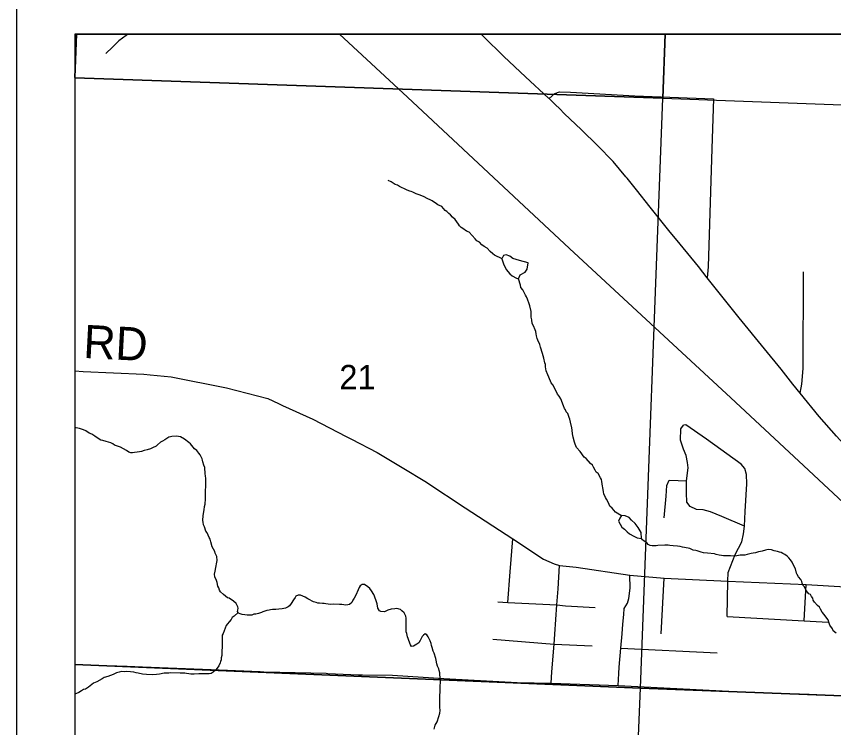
# Model space of a CAD drawing. Extents: x 0 to 34, y 0 to 22.
# Drawn here: x 2 to 3.4, y 19.712 to 20.931 of the extents above; entities that cross this region are included whole.
import ezdxf

# ---------------------------------------------------------------- set-up
doc = ezdxf.new("R2010")
doc.units = 0
for name, color, linetype in [('Default', 7, 'Continuous'), ('GM_X_City_Street', 7, 'Continuous'), ('GM_X_County_Road', 7, 'Continuous'), ('GM_X_County_Road_Text', 7, 'Continuous'), ('GM_X_Minor_River', 7, 'Continuous'), ('GM_X_Rail_Line', 7, 'Continuous'), ('GM_X_Section', 7, 'Continuous'), ('GM_X_Section_Text', 7, 'Continuous'), ('GM_X_US_Route', 7, 'Continuous'), ('SH_Data', 7, 'Continuous')]:
    doc.layers.add(name, color=color, linetype=linetype)

msp = doc.modelspace()

# ---------------------------------------------------------------- linework, layer by layer
at = {"layer": 'Default'}
for points in [[(2.1028, 20.9), (2.1, 20.9), (2.1, 20.8261)], [(2.1, 20.8261), (2.1, 20.8252), (3.1076, 20.7906), (3.1115, 20.9), (2.1028, 20.9)], [(4.1106, 20.9), (3.1115, 20.9), (3.1076, 20.7906), (4.105, 20.7535)], [(2.1, 20.8252), (2.1, 19.8201), (3.0692, 19.7796), (3.1076, 20.7906)], [(2.1, 19.8201), (2.1, 18.8072), (3.0273, 18.7832), (3.0692, 19.7796)]]:
    msp.add_lwpolyline(points, close=True, dxfattribs=at)
msp.add_lwpolyline([(6.0871, 20.9), (2.1, 20.9), (2.1, 17.8044), (2.8305, 17.7727), (2.976, 17.7664), (3.1037, 17.7609), (3.4544, 17.7458), (3.7662, 17.7368), (3.9904, 17.7296), (4.1165, 17.7286), (4.1238, 17.7269), (4.1354, 17.7264), (4.1969, 17.7246), (4.2769, 17.7222), (4.4203, 17.718), (4.506, 17.7155), (4.6237, 17.7121), (4.6735, 17.7102), (4.763, 17.7084), (4.9045, 17.7039), (4.98, 17.7015), (5.0396, 17.6997)], dxfattribs=at)
at = {"layer": 'GM_X_City_Street'}
for p, q in [((3.1047, 19.8726), (3.1096, 19.9678)), ((3.2177, 19.9023), (3.2187, 19.9627)), ((3.3493, 19.895), (3.3527, 19.9573)), ((3.0356, 19.8482), (3.2002, 19.8402))]:
    msp.add_line(p, q, dxfattribs=at)
for points in [[(2.9126, 20.7897), (2.9223, 20.7987), (2.9306, 20.8011), (2.9494, 20.8007), (3.0593, 20.7945), (3.194, 20.7893), (3.1915, 20.7042), (3.1849, 20.5014), (3.1832, 20.4828)], [(3.3427, 20.2852), (3.3456, 20.3005), (3.3478, 20.327), (3.3485, 20.4931)], [(3.2187, 19.9627), (3.2194, 19.9774), (3.2313, 20.0085), (3.2426, 20.0305), (3.2454, 20.044), (3.247, 20.0569), (3.2086, 20.0739), (3.1891, 20.0815), (3.1765, 20.0848), (3.1651, 20.0855), (3.1542, 20.0907), (3.1486, 20.0984), (3.1477, 20.114), (3.1481, 20.1346), (3.1505, 20.1573), (3.1496, 20.1663), (3.1473, 20.1784), (3.1429, 20.189), (3.1379, 20.2044), (3.138, 20.2236), (3.1426, 20.23)], [(3.247, 20.0569), (3.2486, 20.082), (3.2515, 20.1294), (3.2504, 20.1454), (3.2479, 20.156), (3.2418, 20.1634), (3.182, 20.2063), (3.1469, 20.2307), (3.1426, 20.23)], [(3.1099, 20.0714), (3.1128, 20.1086), (3.114, 20.127), (3.118, 20.136), (3.1335, 20.1355), (3.1481, 20.1346)], [(2.8416, 19.926), (2.8456, 19.9787), (2.8505, 20.0351)], [(2.9159, 19.7881), (2.9174, 19.8072), (2.9214, 19.8548), (2.9226, 19.872), (2.926, 19.9222), (2.9278, 19.9497), (2.9306, 19.9898)], [(3.031, 19.7839), (3.0322, 19.8047), (3.0328, 19.8157), (3.0356, 19.8482), (3.0375, 19.8723), (3.0389, 19.8894), (3.0404, 19.9058), (3.0414, 19.9161), (3.0466, 19.9254), (3.049, 19.9331), (3.0515, 19.9507), (3.0508, 19.9729)], [(2.8245, 19.9273), (2.8416, 19.926), (2.926, 19.9222), (2.9406, 19.9208), (2.9914, 19.9179)], [(3.2177, 19.9023), (3.3493, 19.895), (3.3903, 19.8928)], [(2.816, 19.8635), (2.9214, 19.8548), (2.9862, 19.8521)]]:
    msp.add_lwpolyline(points, dxfattribs=at)
at = {"layer": 'GM_X_County_Road'}
for p, q in [((2.216, 19.816), (2.3339, 19.8113)), ((2.3339, 19.8113), (2.4178, 19.808)), ((2.5337, 19.8047), (2.586, 19.8025))]:
    msp.add_line(p, q, dxfattribs=at)
for points in [[(2.1, 20.323), (2.1144, 20.322), (2.2182, 20.3175), (2.2291, 20.3164), (2.2654, 20.3127), (2.3602, 20.2942), (2.4307, 20.2758), (2.4489, 20.2673)], [(2.4489, 20.2673), (2.4561, 20.2639), (2.5076, 20.2406), (2.5649, 20.2107)], [(2.5649, 20.2107), (2.5738, 20.2061), (2.6178, 20.1834), (2.6607, 20.1577), (2.7024, 20.1322), (2.7032, 20.1317)], [(2.7032, 20.1317), (2.7688, 20.0887), (2.8505, 20.0351), (2.9032, 20.0007), (2.921, 19.9928), (2.9306, 19.9898), (2.9591, 19.9866), (3.0508, 19.9729), (3.1096, 19.9678), (3.2187, 19.9627), (3.3527, 19.9573), (3.4202, 19.9534), (3.5026, 19.9485), (3.5475, 19.9479)], [(2.1, 19.8203), (2.1901, 19.817), (2.216, 19.816)], [(2.4178, 19.808), (2.4238, 19.8077), (2.4516, 19.8068), (2.5307, 19.8049), (2.5337, 19.8047)], [(2.586, 19.8025), (2.589, 19.8024), (2.593, 19.8023)], [(2.593, 19.8023), (2.6445, 19.8016), (2.7407, 19.7957), (2.7427, 19.7956)], [(2.7427, 19.7956), (2.8581, 19.789), (2.9159, 19.7881), (3.031, 19.7839), (3.2427, 19.773), (3.3579, 19.7693), (3.4112, 19.7668), (3.4626, 19.7644), (3.491, 19.7643), (3.5023, 19.762), (3.5178, 19.7556), (3.5325, 19.7466), (3.5599, 19.7323), (3.5753, 19.7319)]]:
    msp.add_lwpolyline(points, dxfattribs=at)
at = {"layer": 'GM_X_Minor_River'}
for points in [[(2.1913, 20.9), (2.1882, 20.898), (2.1758, 20.8888), (2.1646, 20.8781), (2.1533, 20.867)], [(2.8319, 20.5154), (2.8189, 20.5215), (2.8163, 20.5239), (2.8115, 20.5275), (2.8063, 20.5333), (2.8011, 20.5362), (2.7974, 20.5394), (2.7933, 20.5437), (2.7888, 20.5458), (2.7859, 20.5497), (2.7756, 20.5607), (2.7711, 20.5627), (2.7647, 20.5672), (2.7618, 20.5688), (2.7588, 20.5716), (2.7574, 20.5747), (2.7519, 20.5825), (2.7471, 20.5868), (2.7438, 20.5907), (2.7408, 20.5927), (2.7371, 20.5963), (2.7345, 20.5983), (2.7286, 20.6046), (2.7222, 20.6079), (2.7196, 20.6095), (2.7125, 20.6143), (2.7099, 20.6159), (2.7035, 20.6188), (2.6987, 20.6212), (2.6919, 20.6241), (2.6885, 20.6254), (2.6851, 20.6263), (2.6791, 20.6292), (2.6765, 20.6304), (2.6738, 20.6312), (2.6697, 20.6329), (2.6671, 20.6341), (2.6637, 20.6358), (2.6607, 20.637), (2.6565, 20.6391), (2.6528, 20.6415), (2.6487, 20.6428), (2.6457, 20.6448), (2.6419, 20.6472), (2.6369, 20.6495)], [(2.8599, 20.481), (2.8629, 20.4878), (2.8717, 20.4921), (2.8749, 20.4977), (2.8767, 20.5083), (2.8616, 20.5124), (2.8507, 20.5158), (2.8455, 20.5197), (2.8391, 20.5221), (2.8342, 20.5207), (2.8317, 20.5151), (2.8346, 20.5067), (2.8392, 20.4971), (2.8455, 20.4897)], [(2.8455, 20.4897), (2.8492, 20.4862), (2.8567, 20.4818), (2.8599, 20.481)], [(2.9119, 20.3125), (2.9101, 20.3164), (2.9073, 20.3234), (2.9064, 20.3303), (2.9061, 20.3341), (2.9054, 20.3372), (2.9034, 20.3448), (2.9024, 20.3491), (2.901, 20.3529), (2.898, 20.3641), (2.8966, 20.3683), (2.8934, 20.3757), (2.8919, 20.3784), (2.891, 20.383), (2.8903, 20.3864), (2.8897, 20.3907), (2.8886, 20.3937), (2.8858, 20.4003), (2.8837, 20.4046), (2.8827, 20.4107), (2.8821, 20.4153), (2.8819, 20.4195), (2.8817, 20.4252), (2.8793, 20.4348), (2.8783, 20.4379), (2.8755, 20.446), (2.8741, 20.4499), (2.8723, 20.453), (2.8673, 20.4623), (2.8644, 20.4662), (2.8638, 20.4703), (2.8599, 20.481)], [(3.0366, 20.075), (3.0263, 20.0809), (3.0203, 20.0878), (3.0166, 20.0914), (3.0152, 20.0941), (3.0145, 20.0968), (3.0109, 20.1034), (3.0091, 20.1061), (3.0063, 20.1127), (3.0056, 20.1158), (3.0043, 20.1231), (3.004, 20.1257), (3.0028, 20.1338), (3.0021, 20.1369), (3.0007, 20.14), (2.9964, 20.1473), (2.993, 20.1497), (2.9912, 20.1529), (2.9887, 20.1579), (2.9869, 20.1614), (2.9836, 20.1645), (2.9762, 20.1728), (2.9725, 20.1756), (2.9656, 20.185), (2.9593, 20.1917), (2.9572, 20.1975), (2.9562, 20.2009), (2.9538, 20.2094), (2.9525, 20.2151), (2.9519, 20.2216), (2.9513, 20.2255), (2.9493, 20.2354), (2.948, 20.2404), (2.9469, 20.2431), (2.9445, 20.2501), (2.9419, 20.2528), (2.9409, 20.2563), (2.9387, 20.259), (2.9373, 20.2633), (2.9327, 20.2753), (2.9299, 20.2799), (2.9269, 20.2835), (2.9216, 20.2943), (2.9191, 20.2993), (2.9161, 20.3029), (2.9119, 20.3125)], [(2.3467, 19.9514), (2.3453, 19.9545), (2.344, 19.9607), (2.3426, 19.9637), (2.3397, 19.9703), (2.3395, 19.9749), (2.3404, 19.9798), (2.3418, 19.9863), (2.3432, 19.9953), (2.3437, 19.998), (2.3432, 20.0049), (2.3403, 20.0107), (2.34, 20.0134), (2.3375, 20.0176), (2.3357, 20.0215), (2.333, 20.0304), (2.332, 20.0346), (2.3302, 20.0377), (2.3266, 20.0454), (2.3248, 20.0486), (2.3224, 20.0559), (2.3206, 20.0594), (2.32, 20.064), (2.3197, 20.067), (2.32, 20.0754), (2.3215, 20.0852), (2.3224, 20.0905), (2.3233, 20.0947), (2.324, 20.1042), (2.3242, 20.1103), (2.3239, 20.1137), (2.3245, 20.1297), (2.3244, 20.1392), (2.3238, 20.1427), (2.3235, 20.1473), (2.3233, 20.1507), (2.323, 20.1534), (2.3227, 20.1576), (2.3213, 20.1618), (2.3196, 20.1672), (2.3189, 20.1699), (2.3183, 20.1726), (2.3151, 20.1792), (2.3125, 20.1823), (2.3092, 20.1866), (2.3051, 20.1898), (2.3007, 20.1953), (2.2985, 20.1984), (2.2956, 20.2004), (2.2881, 20.2064), (2.281, 20.2101), (2.278, 20.2109), (2.2746, 20.2114), (2.2665, 20.211), (2.2638, 20.2103), (2.2611, 20.2096), (2.2541, 20.2049), (2.2506, 20.2027), (2.2471, 20.201), (2.242, 20.1962), (2.2393, 20.1944), (2.2334, 20.1911), (2.2296, 20.1898), (2.2242, 20.188), (2.2188, 20.1867), (2.2146, 20.1853), (2.2107, 20.1847), (2.2069, 20.1837), (2.2023, 20.1831), (2.1992, 20.1828), (2.1962, 20.1829), (2.1928, 20.1838), (2.1887, 20.1866), (2.1786, 20.1923), (2.1752, 20.1935), (2.168, 20.1961), (2.1654, 20.1981), (2.1616, 20.1997), (2.1541, 20.2023), (2.148, 20.2036), (2.145, 20.2045), (2.1383, 20.2085), (2.1342, 20.2113), (2.1293, 20.2145), (2.1248, 20.2166), (2.1189, 20.2206), (2.1151, 20.2219), (2.1083, 20.2244), (2.1022, 20.2254), (2.1, 20.2257)], [(3.0708, 20.0358), (3.0705, 20.0462), (3.065, 20.0547), (3.0599, 20.0617), (3.0539, 20.0675), (3.0495, 20.0722), (3.0428, 20.0746), (3.0367, 20.0751), (3.0336, 20.0707), (3.0315, 20.0658), (3.037, 20.0554), (3.0418, 20.0519)], [(3.0418, 20.0519), (3.0462, 20.0476), (3.0503, 20.0437), (3.0574, 20.0397), (3.0634, 20.0373), (3.0708, 20.0358)], [(3.2776, 20.0142), (3.2745, 20.0136), (3.2715, 20.0133), (3.2661, 20.0112), (3.2622, 20.0109), (3.2588, 20.0103), (3.2519, 20.0086), (3.2476, 20.0076), (3.2427, 20.0074), (3.24, 20.0075), (3.2342, 20.0062), (3.2304, 20.0059), (3.2232, 20.0062), (3.2182, 20.006), (3.2114, 20.0062), (3.2076, 20.0067), (3.2038, 20.0076), (3.1985, 20.0086), (3.1958, 20.0098), (3.1837, 20.011), (3.1772, 20.0112), (3.173, 20.0125), (3.1662, 20.0146), (3.1636, 20.0151), (3.1594, 20.016), (3.1534, 20.0189), (3.1447, 20.0207), (3.1413, 20.0212), (3.1371, 20.0221), (3.1322, 20.023), (3.125, 20.0233), (3.1193, 20.0242), (3.1166, 20.0243), (3.1105, 20.0245), (3.099, 20.0238), (3.096, 20.0231), (3.0926, 20.0236), (3.0891, 20.0234), (3.0857, 20.0239), (3.0823, 20.0255), (3.0798, 20.0287), (3.0753, 20.0315), (3.0727, 20.0335), (3.0708, 20.0358)], [(3.4045, 19.8735), (3.3993, 19.8778), (3.3979, 19.8809), (3.3935, 19.8875), (3.3925, 19.8906), (3.3904, 19.8964), (3.3864, 19.9015), (3.3838, 19.9058), (3.3805, 19.9097), (3.3777, 19.9148), (3.3755, 19.9183), (3.3722, 19.9214), (3.367, 19.9269), (3.3648, 19.9304), (3.3642, 19.9335), (3.362, 19.9366), (3.3602, 19.9398), (3.3576, 19.9414), (3.355, 19.9437), (3.3528, 19.9469), (3.3499, 19.9531), (3.3474, 19.9558), (3.346, 19.9593), (3.3453, 19.9624), (3.3439, 19.9655), (3.3395, 19.9702), (3.3377, 19.9741), (3.3362, 19.9768), (3.3346, 19.9841), (3.3314, 19.9903), (3.3289, 19.9953), (3.3259, 19.9992), (3.3234, 20.0027), (3.3201, 20.0059), (3.3163, 20.0083), (3.313, 20.0103), (3.31, 20.012), (3.3073, 20.0128), (3.3039, 20.0137), (3.2979, 20.015), (3.2933, 20.0167), (3.2876, 20.0169), (3.283, 20.0159), (3.2776, 20.0142)], [(2.6767, 19.8509), (2.6753, 19.854), (2.6721, 19.8613), (2.6711, 19.8648), (2.6701, 19.8675), (2.6687, 19.8733), (2.668, 19.876), (2.6676, 19.8844), (2.6679, 19.8954), (2.6677, 19.8992), (2.667, 19.9027), (2.6642, 19.9085), (2.6605, 19.912), (2.6579, 19.9144), (2.6515, 19.9158), (2.6484, 19.9155), (2.6419, 19.9146), (2.6365, 19.9129), (2.6338, 19.9118), (2.6307, 19.9104), (2.6246, 19.9106), (2.622, 19.9122), (2.6191, 19.9165), (2.6178, 19.9242), (2.6168, 19.9276), (2.6136, 19.9373), (2.6122, 19.94), (2.6082, 19.9462), (2.6057, 19.9501), (2.6023, 19.9529), (2.5964, 19.9569), (2.5926, 19.957), (2.5891, 19.9549), (2.5871, 19.9519), (2.5854, 19.9481), (2.5813, 19.9391), (2.5788, 19.9335), (2.5764, 19.9305), (2.5744, 19.9264), (2.5704, 19.9228), (2.5677, 19.9221), (2.5643, 19.9218), (2.5575, 19.9228), (2.5537, 19.9229), (2.543, 19.9233), (2.5384, 19.9231), (2.5339, 19.9236), (2.5304, 19.9241), (2.5274, 19.9246), (2.5244, 19.9247), (2.5194, 19.9253), (2.5164, 19.9254), (2.5137, 19.9262), (2.5092, 19.9275), (2.5065, 19.9284), (2.5028, 19.9308), (2.4995, 19.9328), (2.495, 19.9353), (2.4908, 19.9373), (2.4867, 19.9386), (2.4829, 19.9387), (2.479, 19.9373), (2.4774, 19.9347), (2.475, 19.9306), (2.4709, 19.9243), (2.4681, 19.9206), (2.4654, 19.9188), (2.4608, 19.9166), (2.4554, 19.9153), (2.4496, 19.9147), (2.4447, 19.9141), (2.442, 19.9142), (2.4386, 19.914), (2.4355, 19.9137), (2.4328, 19.913), (2.4293, 19.9124), (2.4224, 19.9103), (2.4197, 19.9089), (2.4147, 19.9072), (2.4104, 19.9062), (2.407, 19.9063), (2.4031, 19.9045), (2.3989, 19.9043), (2.3955, 19.9044), (2.3913, 19.9053), (2.3868, 19.9058), (2.3834, 19.9067), (2.3804, 19.908), (2.3786, 19.9107), (2.3794, 19.9133), (2.3799, 19.9164), (2.3796, 19.919), (2.3764, 19.9245), (2.3719, 19.9288), (2.3645, 19.9337), (2.3618, 19.9345), (2.3581, 19.9369), (2.3551, 19.9397), (2.3496, 19.9445), (2.3481, 19.9476), (2.3467, 19.9514)], [(2.3797, 19.909), (2.3733, 19.9029), (2.3698, 19.9003), (2.3678, 19.8973), (2.3646, 19.8933), (2.3615, 19.8896), (2.3594, 19.8866), (2.3574, 19.8821), (2.3557, 19.878), (2.354, 19.8731), (2.3528, 19.8701), (2.3526, 19.864), (2.3525, 19.8609), (2.3528, 19.8579), (2.352, 19.8354), (2.3511, 19.8313), (2.3506, 19.8282), (2.3498, 19.8252), (2.3493, 19.8226), (2.3468, 19.8177), (2.3441, 19.814), (2.3409, 19.8103), (2.3373, 19.807), (2.3338, 19.8048), (2.3304, 19.8042), (2.3269, 19.8039), (2.3235, 19.804), (2.3189, 19.8038), (2.3124, 19.804), (2.3048, 19.8035), (2.2987, 19.8037), (2.2957, 19.8042), (2.2915, 19.8047), (2.2885, 19.8052), (2.2846, 19.8053), (2.2804, 19.8051), (2.2637, 19.8057), (2.261, 19.8054), (2.2572, 19.8052), (2.253, 19.8049), (2.2453, 19.8033), (2.2399, 19.8027), (2.2334, 19.8025), (2.2228, 19.8029), (2.2163, 19.8035), (2.2087, 19.8049), (2.2053, 19.8058), (2.2012, 19.8067), (2.1958, 19.8073), (2.1886, 19.8079), (2.1844, 19.8077), (2.1802, 19.8078), (2.176, 19.8068), (2.1714, 19.8058), (2.1656, 19.803), (2.1567, 19.7995), (2.1505, 19.7978), (2.147, 19.7956), (2.1377, 19.7902), (2.1323, 19.7881), (2.1291, 19.7856), (2.1236, 19.7812), (2.1186, 19.7779), (2.1151, 19.7773), (2.1116, 19.7747), (2.1069, 19.7722), (2.1, 19.7691)], [(2.7155, 19.7094), (2.7168, 19.7135), (2.7176, 19.7161), (2.7209, 19.7217), (2.7235, 19.7308), (2.7256, 19.7368), (2.7257, 19.741), (2.7255, 19.7467), (2.7256, 19.7494), (2.7255, 19.7566), (2.7256, 19.7593), (2.7254, 19.7646), (2.7257, 19.7757), (2.7259, 19.7814), (2.7263, 19.7917), (2.7261, 19.7989), (2.7255, 19.802), (2.7252, 19.8058), (2.7242, 19.81), (2.7239, 19.8127), (2.7214, 19.8174), (2.7204, 19.8212), (2.7191, 19.8277), (2.7188, 19.8304), (2.7156, 19.8393), (2.7139, 19.8431), (2.7125, 19.8489), (2.7111, 19.8524), (2.7105, 19.8562), (2.7087, 19.8605), (2.7073, 19.8639), (2.7055, 19.8674), (2.703, 19.8706), (2.7004, 19.8726), (2.6976, 19.8704), (2.6952, 19.8678), (2.6916, 19.8611), (2.6892, 19.8573), (2.686, 19.8548), (2.6833, 19.853), (2.6802, 19.8512), (2.6767, 19.8509)]]:
    msp.add_lwpolyline(points, dxfattribs=at)
at = {"layer": 'GM_X_Rail_Line'}
msp.add_lwpolyline([(2.5538, 20.9), (2.6699, 20.7921), (2.9476, 20.533), (3.1327, 20.3614), (3.2237, 20.277), (3.3405, 20.1683), (3.4419, 20.0737), (3.4898, 20.0243), (3.5092, 20.0023), (3.5538, 19.9473), (3.6006, 19.8809), (3.6088, 19.8671), (3.6176, 19.8515), (3.6298, 19.8303), (3.6768, 19.7476), (3.7408, 19.633), (3.7622, 19.5944), (3.79, 19.5454), (4.1053, 18.9832), (4.1141, 18.9644), (4.1259, 18.9412), (4.1333, 18.9272), (4.1473, 18.9034)], dxfattribs=at)
at = {"layer": 'GM_X_Section'}
for points in [[(3.1076, 20.7906), (4.105, 20.7535), (4.0623, 19.7415), (3.0692, 19.7796)], [(3.0692, 19.7796), (4.0623, 19.7415), (4.0218, 18.7461), (3.0273, 18.7832)]]:
    msp.add_lwpolyline(points, close=True, dxfattribs=at)
at = {"layer": 'GM_X_US_Route'}
for points in [[(2.9118, 20.7904), (2.8721, 20.8272), (2.835, 20.862), (2.7999, 20.8962), (2.7959, 20.9)], [(3.0461, 20.6532), (3.0441, 20.6555), (3.0222, 20.682), (2.9957, 20.7094), (2.968, 20.736), (2.9385, 20.7645), (2.9308, 20.7721), (2.9228, 20.7797), (2.9126, 20.7897), (2.9118, 20.7904)], [(3.6109, 20.0177), (3.5908, 20.0186), (3.5719, 20.0323), (3.5498, 20.0557), (3.5175, 20.0904), (3.5057, 20.1023), (3.4828, 20.127), (3.4484, 20.1637), (3.4051, 20.2112), (3.3749, 20.2451), (3.3427, 20.2852), (3.3299, 20.3005), (3.3099, 20.3263), (3.2816, 20.3609), (3.238, 20.4139), (3.2083, 20.4514), (3.1832, 20.4828), (3.1686, 20.5019), (3.137, 20.5404), (3.1178, 20.5639), (3.0859, 20.6036), (3.062, 20.6335), (3.0461, 20.6532)]]:
    msp.add_lwpolyline(points, dxfattribs=at)
at = {"layer": 'SH_Data'}
for p, q in [((2, 21), (2, 14)), ((2.1, 20.9), (2.1, 14.1)), ((2.1, 20.9), (8.9, 20.9))]:
    msp.add_line(p, q, dxfattribs=at)

# ---------------------------------------------------------------- texts
at = {"layer": 'GM_X_County_Road_Text'}
msp.add_text('RD', height=0.05682, rotation=357.0388, dxfattribs=at).set_placement((2.1139, 20.3455))
at = {"layer": 'GM_X_Section_Text'}
msp.add_text('21', height=0.04186, rotation=0, dxfattribs=at).set_placement((2.5532, 20.2915))

doc.saveas('drawing.dxf')
